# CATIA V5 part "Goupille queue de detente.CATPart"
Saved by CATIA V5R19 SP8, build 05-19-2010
Part number: Goupille queue de détente
Bounding box of the stored display mesh (mm): x 0 to 29, y -2 to 2, z -2 to 2
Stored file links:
  C:\Users\Arthur\Desktop\Catia parts\GLOCK\Poignée\Goupille queue de detente.CATPart
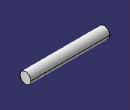
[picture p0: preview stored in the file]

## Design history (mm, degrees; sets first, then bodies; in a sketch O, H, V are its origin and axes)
Set1
  Sketch1 on yz-plane, origin (0, 0, 0), H (0, 1, 0), V (0, 0, 1)
    circle A1 centre (0, 0) radius 2
    radius A1 = 2
Body1 (main body)
  Pad1: profile Sketch1, direction (1, 0, 0), length 29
